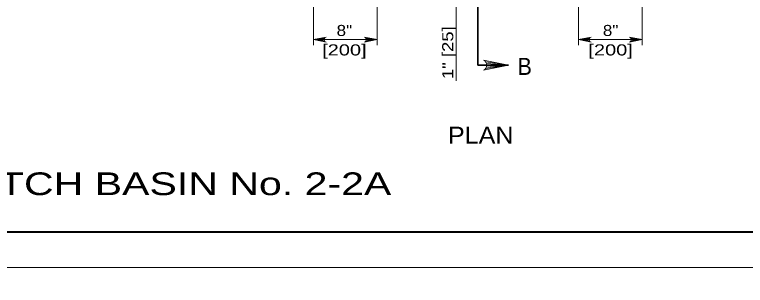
# Model space of a CAD drawing. Extents: x -410.5 to -376.5, y 1617.6 to 1661.6.
# Drawn here: x -398.98 to -388.7, y 1639.31 to 1643.13 of the extents above; entities that cross this region are included whole.
import ezdxf
from ezdxf.enums import TextEntityAlignment as Align

# ---------------------------------------------------------------- set-up
doc = ezdxf.new("R2010")
doc.units = 0
doc.header["$LTSCALE"] = 0.062
doc.linetypes.add('LONG_DASHED', pattern=[7.5, 6, -1.5])
doc.layers.add('1', color=7, linetype='Continuous', lineweight=13)

msp = doc.modelspace()

# ---------------------------------------------------------------- linework, layer by layer
at = {"layer": '1'}
for p, q in [((-393.8805, 1644.31383), (-393.8805, 1642.69608)), ((-391.0485, 1644.31383), (-391.0485, 1642.69608)), ((-392.77125, 1643.41433), (-392.77125, 1642.19508)), ((-394.77725, 1643.33567), (-394.77725, 1642.69608)), ((-390.15167, 1643.33575), (-390.15167, 1642.69608)), ((-394.617, 1642.79717), (-394.77725, 1642.77475)), ((-394.62242, 1642.78608), (-394.77725, 1642.77475)), ((-394.62408, 1642.77475), (-394.77725, 1642.77475)), ((-394.62125, 1642.76033), (-394.77725, 1642.77475)), ((-394.61517, 1642.74992), (-394.77725, 1642.77475)), ((-394.04258, 1642.74992), (-393.8805, 1642.77475)), ((-394.04067, 1642.79717), (-393.8805, 1642.77475)), ((-394.0365, 1642.76033), (-393.8805, 1642.77475)), ((-394.03525, 1642.78608), (-393.8805, 1642.77475)), ((-394.03367, 1642.77475), (-393.8805, 1642.77475)), ((-390.88825, 1642.79717), (-391.0485, 1642.77475)), ((-390.89367, 1642.78608), (-391.0485, 1642.77475)), ((-390.89533, 1642.77475), (-391.0485, 1642.77475)), ((-390.8925, 1642.76033), (-391.0485, 1642.77475)), ((-390.88633, 1642.74992), (-391.0485, 1642.77475)), ((-390.31383, 1642.74992), (-390.15167, 1642.77475)), ((-390.31192, 1642.79717), (-390.15167, 1642.77475)), ((-390.30767, 1642.76033), (-390.15167, 1642.77475)), ((-390.3065, 1642.78608), (-390.15167, 1642.77475)), ((-390.30483, 1642.77475), (-390.15167, 1642.77475)), ((-392.35225, 1642.45975), (-392.03183, 1642.41492)), ((-392.35608, 1642.36542), (-392.03183, 1642.41492)), ((-392.34375, 1642.38617), (-392.03183, 1642.41492)), ((-392.34142, 1642.43758), (-392.03183, 1642.41492)), ((-392.33808, 1642.41492), (-392.03183, 1642.41492))]:
    msp.add_line(p, q, dxfattribs=at)
at = {"layer": '1', "lineweight": 35}
msp.add_line((-392.4645, 1642.41492), (-392.03183, 1642.41492), dxfattribs=at)
at = {"layer": '1', "linetype": 'LONG_DASHED'}
for points in [[(-410.45475, 1639.56183), (-376.45475, 1639.56183), (-376.45475, 1661.56183), (-410.45475, 1661.56183)], [(-410.45475, 1617.56183), (-376.45475, 1617.56183), (-376.45475, 1639.56183), (-410.45475, 1639.56183)]]:
    msp.add_lwpolyline(points, close=True, dxfattribs=at)
at = {"layer": '1', "lineweight": 25}
msp.add_lwpolyline([(-376.95475, 1640.06183), (-408.45475, 1640.06183), (-408.45475, 1661.06183)], dxfattribs=at)
at = {"layer": '1', "lineweight": 40}
msp.add_lwpolyline([(-408.45475, 1661.06183), (-376.95475, 1661.06183), (-376.95475, 1640.06183), (-408.45475, 1640.06183)], close=True, dxfattribs=at)
msp.add_lwpolyline([(-408.45475, 1661.06183), (-376.95475, 1661.06183), (-376.95475, 1640.06183), (-408.45475, 1640.06183)], close=True, dxfattribs=at)
at = {"layer": '1', "lineweight": 35}
msp.add_lwpolyline([(-392.4645, 1642.41492), (-392.4645, 1642.7695), (-392.4645, 1646.65875)], dxfattribs=at)
at = {"layer": '1'}
for points in [[(-394.60025, 1642.73933), (-394.77725, 1642.77475), (-394.60025, 1642.81008)], [(-393.8805, 1642.77475), (-394.20067, 1642.77475), (-394.77725, 1642.77475)], [(-394.0575, 1642.73933), (-393.8805, 1642.77475), (-394.0575, 1642.81008)], [(-390.8715, 1642.73933), (-391.0485, 1642.77475), (-390.8715, 1642.81008)], [(-390.15167, 1642.77475), (-390.47183, 1642.77475), (-391.0485, 1642.77475)], [(-390.32867, 1642.73933), (-390.15167, 1642.77475), (-390.32867, 1642.81008)], [(-392.38583, 1642.34417), (-392.03183, 1642.41492), (-392.38583, 1642.48575)]]:
    msp.add_lwpolyline(points, dxfattribs=at)
for centre, radius, start, end in [((-394.58597, 1642.77476), 0.0382, 112.08782, 247.91395), ((-394.07176, 1642.77476), 0.0382, 292.08605, 67.91218), ((-390.85717, 1642.77476), 0.0382, 112.08782, 247.91395), ((-390.34296, 1642.77476), 0.0382, 292.08605, 67.91218), ((-392.41438, 1642.41502), 0.0764, 292.08605, 67.91218)]:
    msp.add_arc(centre, radius, start, end, dxfattribs=at)

# ---------------------------------------------------------------- texts
for s, height, width, p in [('8"', 0.156, 1.15, (-394.34225, 1642.82558)), ('8"', 0.156, 1.15, (-390.59608, 1642.82558)), ('[200]', 0.156, 1.35, (-394.34225, 1642.55158)), ('[200]', 0.156, 1.35, (-390.59608, 1642.55158)), ('B', 0.24, 0.95, (-391.80533, 1642.2775)), ('CATCH BASIN No. 2-2A', 0.32, 1.35, (-396.8435, 1640.58383))]:
    msp.add_text(s, height=height, dxfattribs=dict(at, width=width)).set_placement(p, align=Align.CENTER)
at = {"layer": '1', "width": 1.25}
msp.add_text('1" [25]', height=0.156, rotation=90, dxfattribs=at).set_placement((-392.80992, 1642.21825))
at = {"layer": '1', "width": 1.1}
msp.add_text('PLAN', height=0.24, dxfattribs=at).set_placement((-392.88458, 1641.30808))

doc.saveas('drawing.dxf')
